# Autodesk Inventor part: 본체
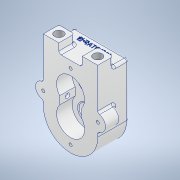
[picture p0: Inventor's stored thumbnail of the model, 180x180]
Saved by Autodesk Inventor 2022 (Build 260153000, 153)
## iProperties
Created: 2024-03
Part Number: 본체
Material: 알루미늄 6061
Document SubType Name: Modeling
Designer: PC-12
Density: 2.7 g/cm^3
Appearance: 알루미늄 - 평지
Mass: 641.967 g
Surface Area: 392.13 cm^2
Volume: 237.765 cm^3
Author: PC-12
## Parameters: d0 = 35 mm, d2 = 33 mm, d4 = 0, d7 = 12 mm, d8 = 0, d11 = 63.5 mm, d13 = 0, d14 = 52 mm, d15 = 6 mm, d16 = 0, d17 = 32 mm, d18 = 4 mm, d19 = 0, d21 = 36 mm, d22 = 36 mm, d23 = 33 mm, d24 = 28 mm, d25 = 14 mm, d27 = 0, d31 = 0, d32 = 15 mm, d33 = 0, d34 = 0, d35 = 25 mm, d36 = 7.3 mm, d37 = 0, d38 = 14 mm, d39 = 7.3 mm, d40 = -60 deg, d41 = 3 mm, d42 = 1 mm, d43 = 2 mm, d44 = 45 deg, d45 = -0.7 mm, d46 = 7.3 mm, d47 = 30 deg, d48 = 6 mm, d49 = 6 mm, d51 = 25 mm, d54 = 63.5 mm, d55 = 63.5 mm, d56 = 8 mm, d57 = 0, d58 = 0, d59 = 4.134 mm, d61 = 4 mm, d62 = 2 mm, d63 = 90 deg, d64 = 12 mm, d65 = 118 deg, d66 = 26 mm, d67 = 59 mm, d68 = 42 mm, d69 = 3.242 mm, d70 = 8 mm, d71 = 4 mm, d72 = 2 mm, d73 = 90 deg, d75 = 118 deg, d76 = 11.445 mm, d77 = 13 mm, d78 = 4 mm, d79 = 2 mm, d80 = 90 deg, d81 = 16 mm, d82 = 118 deg, d83 = 1 mm, d84 = 2 mm, d85 = 45 deg, d87 = 0.5 mm, d88 = 0
